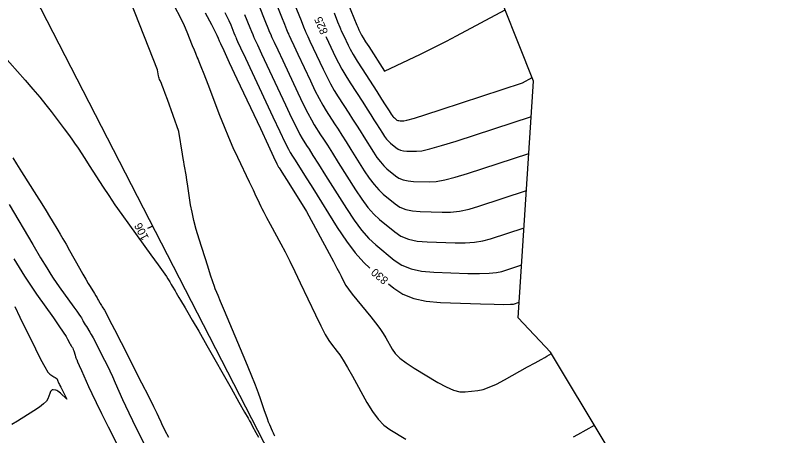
# Model space of a CAD drawing. Extents: x 1715724 to 1716561, y 394063 to 395906.
# Drawn here: x 1716070.7 to 1716206.5, y 394949.5 to 395022.9 of the extents above; entities that cross this region are included whole.
import ezdxf

# ---------------------------------------------------------------- set-up
doc = ezdxf.new("R2010")
doc.units = 0
for name, color, linetype in [('DT_X_Contour_Major', 7, 'Continuous'), ('DT_X_Contour_Minor', 7, 'Continuous'), ('DT_X_TIN_Hull', 7, 'Continuous'), ('GE_P_CL_10', 7, 'Continuous')]:
    doc.layers.add(name, color=color, linetype=linetype)

msp = doc.modelspace()

# ---------------------------------------------------------------- linework, layer by layer
at = {"layer": 'DT_X_Contour_Major'}
for points in [[(1716107.28, 395023.4), (1716107.97, 395022.03), (1716108.33, 395021.24), (1716108.89, 395019.87), (1716109.07, 395019.42), (1716109.2, 395019.09), (1716109.29, 395018.88), (1716109.32, 395018.8), (1716109.35, 395018.73), (1716109.53, 395018.35), (1716110.05, 395017.25), (1716110.9, 395015.44), (1716112.08, 395012.91), (1716115.7, 395005.2), (1716116.9, 395002.65), (1716117.81, 395000.75), (1716118.41, 394999.52), (1716118.72, 394998.95), (1716119.13, 394998.31), (1716119.47, 394997.77), (1716120.17, 394996.66), (1716121.24, 394994.97), (1716122.67, 394992.7), (1716126.96, 394985.85), (1716128.55, 394983.46), (1716130.1, 394981.42), (1716131.59, 394979.73), (1716132.67, 394978.73)], [(1716124.96, 395019.21), (1716125.01, 395019.12), (1716125.41, 395018.25), (1716126.65, 395015.61), (1716127.16, 395014.59), (1716127.75, 395013.5), (1716128.44, 395012.34), (1716129.21, 395011.1), (1716131.4, 395007.73), (1716132.16, 395006.54), (1716132.82, 395005.52), (1716133.37, 395004.66), (1716133.81, 395003.97), (1716134.83, 395002.34), (1716135.21, 395001.77), (1716135.58, 395001.28), (1716135.94, 395000.88), (1716136.28, 395000.56), (1716137.19, 394999.81), (1716137.57, 394999.56), (1716138.01, 394999.38), (1716138.54, 394999.27), (1716139.13, 394999.21), (1716140.81, 394999.16), (1716141.71, 394999.26), (1716143.16, 394999.59), (1716145.16, 395000.16), (1716147.71, 395000.96), (1716160.88, 395005.27)], [(1716070.39, 394980.38), (1716071.31, 394978.86), (1716072.28, 394977.34), (1716073.3, 394975.79), (1716074.38, 394974.24), (1716077.32, 394970.08), (1716078.3, 394968.67), (1716079.04, 394967.59), (1716079.54, 394966.83), (1716079.8, 394966.38), (1716080.18, 394965.61), (1716080.3, 394965.36), (1716080.41, 394965.17), (1716080.48, 394965.05), (1716080.53, 394965), (1716080.63, 394964.94), (1716080.67, 394964.88), (1716080.73, 394964.76), (1716080.8, 394964.57), (1716080.89, 394964.31), (1716081.13, 394963.54), (1716081.21, 394963.29), (1716081.27, 394963.11), (1716081.31, 394963), (1716081.32, 394962.95), (1716081.33, 394962.94), (1716081.39, 394962.8), (1716081.56, 394962.41), (1716081.85, 394961.76), (1716082.25, 394960.86), (1716083.48, 394958.09), (1716084.04, 394956.88), (1716084.8, 394955.29), (1716085.76, 394953.35), (1716086.92, 394951.04), (1716091.41, 394942.22)], [(1716135.89, 394976.05), (1716136.85, 394975.26), (1716138.43, 394974.23), (1716140.31, 394973.47), (1716142.5, 394972.97), (1716144.98, 394972.75), (1716152.02, 394972.53), (1716154.36, 394972.46), (1716156.09, 394972.44), (1716157.22, 394972.45), (1716157.74, 394972.5), (1716158.78, 394972.84)]]:
    msp.add_lwpolyline(points, dxfattribs=at)
at = {"layer": 'DT_X_Contour_Minor'}
for points in [[(1716118.04, 395028.39), (1716120.61, 395022.02), (1716121.07, 395020.89), (1716121.34, 395020.21), (1716121.44, 395019.97), (1716121.45, 395019.94), (1716121.78, 395019.24), (1716122.18, 395018.38), (1716122.75, 395017.18), (1716124.46, 395013.53), (1716125.11, 395012.2), (1716125.76, 395010.95), (1716126.43, 395009.77), (1716127.11, 395008.67), (1716128.95, 395005.84), (1716129.62, 395004.79), (1716130.29, 395003.75), (1716130.94, 395002.72), (1716131.58, 395001.71), (1716133.26, 394999.04), (1716133.88, 394998.11), (1716134.48, 394997.31), (1716135.07, 394996.65), (1716135.63, 394996.12), (1716137.12, 394994.9), (1716137.74, 394994.5), (1716138.47, 394994.2), (1716139.33, 394994.01), (1716140.3, 394993.92), (1716143.05, 394993.83), (1716144.24, 394993.9), (1716145.75, 394994.16), (1716147.57, 394994.62), (1716149.72, 394995.27), (1716160.46, 394998.79)], [(1716115.61, 395026.6), (1716117.2, 395022.66), (1716117.72, 395021.37), (1716118.1, 395020.44), (1716118.33, 395019.88), (1716118.41, 395019.68), (1716118.43, 395019.64), (1716118.54, 395019.41), (1716118.85, 395018.74), (1716119.36, 395017.65), (1716120.08, 395016.11), (1716122.27, 395011.45), (1716123.05, 395009.81), (1716123.77, 395008.4), (1716124.43, 395007.21), (1716125.02, 395006.24), (1716126.49, 395003.96), (1716127.09, 395003.03), (1716127.76, 395001.98), (1716128.51, 395000.79), (1716129.35, 394999.46), (1716131.68, 394995.74), (1716132.55, 394994.45), (1716133.39, 394993.34), (1716134.2, 394992.42), (1716134.99, 394991.69), (1716137.05, 394989.99), (1716137.91, 394989.43), (1716138.93, 394989.02), (1716140.12, 394988.75), (1716141.47, 394988.63), (1716145.29, 394988.51), (1716146.77, 394988.54), (1716148.33, 394988.73), (1716149.99, 394989.08), (1716151.72, 394989.58), (1716160.04, 394992.3)], [(1716128.29, 395026.38), (1716130.38, 395021.2), (1716130.53, 395020.85), (1716130.54, 395020.82), (1716130.74, 395020.39), (1716131.03, 395019.78), (1716131.2, 395019.46), (1716131.49, 395018.97), (1716131.9, 395018.31), (1716132.44, 395017.48), (1716135.22, 395013.17), (1716141.48, 395016.14), (1716142.88, 395016.82), (1716144.4, 395017.58), (1716146.04, 395018.42), (1716147.81, 395019.35), (1716156.31, 395023.89)], [(1716116.03, 394949.43), (1716115.94, 394949.64), (1716115.81, 394949.94), (1716115.64, 394950.31), (1716115.14, 394951.41), (1716114.94, 394951.87), (1716114.73, 394952.43), (1716114.5, 394953.08), (1716114.24, 394953.82), (1716113.55, 394955.93), (1716113.19, 394956.93), (1716112.64, 394958.35), (1716111.89, 394960.2), (1716110.95, 394962.47), (1716108.17, 394969.08), (1716107.25, 394971.28), (1716106.56, 394972.92), (1716106.11, 394974), (1716105.89, 394974.51), (1716105.63, 394975.14), (1716105.47, 394975.57), (1716105.2, 394976.37), (1716104.81, 394977.56), (1716104.31, 394979.13), (1716102.83, 394983.82), (1716102.31, 394985.52), (1716101.89, 394987.08), (1716101.56, 394988.51), (1716101.32, 394989.81), (1716100.81, 394993.1), (1716100.64, 394994.21), (1716100.51, 394995.06), (1716100.41, 394995.66), (1716100.35, 394996), (1716100.26, 394996.58), (1716100.21, 394996.87), (1716100.13, 394997.32), (1716100.03, 394997.93), (1716099.9, 394998.69), (1716099.23, 395002.61), (1716097.25, 395008.2), (1716096.87, 395009.27), (1716096.57, 395010.09), (1716096.36, 395010.66), (1716096.22, 395010.99), (1716095.99, 395011.52), (1716095.9, 395011.72), (1716095.83, 395011.93), (1716095.77, 395012.14), (1716095.72, 395012.35), (1716095.52, 395013.37), (1716090.84, 395025.22)], [(1716098.49, 395024.46), (1716099.47, 395022.59), (1716100.19, 395021.11), (1716100.67, 395020.03), (1716101.61, 395017.64), (1716101.92, 395016.86), (1716102.14, 395016.29), (1716102.28, 395015.94), (1716102.33, 395015.81), (1716102.36, 395015.75), (1716102.37, 395015.72), (1716102.4, 395015.66), (1716102.43, 395015.58), (1716102.48, 395015.48), (1716102.63, 395015.17), (1716102.77, 395014.82), (1716103.1, 395013.98), (1716103.61, 395012.67), (1716104.3, 395010.88), (1716106.38, 395005.46), (1716107.16, 395003.48), (1716107.94, 395001.61), (1716108.71, 394999.84), (1716109.48, 394998.17), (1716111.53, 394993.85), (1716112.22, 394992.41), (1716112.74, 394991.31), (1716113.1, 394990.55), (1716113.29, 394990.15), (1716113.59, 394989.53), (1716113.77, 394989.16), (1716114.11, 394988.53), (1716114.59, 394987.63), (1716115.22, 394986.46), (1716117.09, 394983), (1716117.83, 394981.6), (1716118.64, 394980), (1716119.53, 394978.2), (1716120.49, 394976.2), (1716123.16, 394970.59), (1716124.08, 394968.69), (1716124.85, 394967.2), (1716125.47, 394966.13), (1716125.93, 394965.46), (1716126.94, 394964.23), (1716127.4, 394963.61), (1716127.99, 394962.68), (1716128.73, 394961.43), (1716129.61, 394959.87), (1716132.13, 394955.29), (1716133.1, 394953.71), (1716134.08, 394952.4), (1716135.1, 394951.36), (1716136.14, 394950.59), (1716138.94, 394948.9)], [(1716113.18, 395024.81), (1716114.43, 395021.73), (1716114.84, 395020.72), (1716115.13, 395019.99), (1716115.31, 395019.54), (1716115.38, 395019.38), (1716115.4, 395019.34), (1716115.53, 395019.06), (1716115.91, 395018.25), (1716116.54, 395016.91), (1716117.42, 395015.04), (1716120.08, 395009.37), (1716121, 395007.42), (1716121.79, 395005.85), (1716122.42, 395004.64), (1716122.92, 395003.81), (1716124.04, 395002.07), (1716124.55, 395001.28), (1716125.23, 395000.21), (1716126.09, 394998.85), (1716127.12, 394997.2), (1716130.11, 394992.45), (1716131.22, 394990.79), (1716132.29, 394989.37), (1716133.33, 394988.19), (1716134.34, 394987.25), (1716136.99, 394985.08), (1716138.08, 394984.36), (1716139.39, 394983.83), (1716140.91, 394983.49), (1716142.64, 394983.34), (1716147.54, 394983.18), (1716149.3, 394983.18), (1716150.92, 394983.3), (1716152.4, 394983.53), (1716153.73, 394983.89), (1716159.62, 394985.81)], [(1716103.88, 395023.32), (1716104.96, 395021.3), (1716105.63, 395020.01), (1716105.91, 395019.45), (1716106.11, 395018.94), (1716106.18, 395018.77), (1716106.24, 395018.64), (1716106.27, 395018.55), (1716106.29, 395018.5), (1716106.33, 395018.43), (1716106.53, 395018), (1716107.11, 395016.75), (1716108.08, 395014.7), (1716109.42, 395011.84), (1716113.51, 395003.12), (1716114.85, 395000.26), (1716115.82, 394998.2), (1716116.41, 394996.95), (1716116.62, 394996.51), (1716116.68, 394996.42), (1716116.79, 394996.25), (1716117.07, 394995.79), (1716117.54, 394995.05), (1716118.18, 394994.04), (1716121.57, 394988.64), (1716125.52, 394981.33), (1716126.28, 394979.91), (1716126.89, 394978.78), (1716127.33, 394977.93), (1716127.61, 394977.37), (1716128.14, 394976.25), (1716128.43, 394975.75), (1716128.89, 394975.07), (1716129.54, 394974.22), (1716130.36, 394973.2), (1716132.8, 394970.26), (1716133.65, 394969.2), (1716134.37, 394968.23), (1716134.97, 394967.36), (1716135.44, 394966.58), (1716136.52, 394964.62), (1716137.07, 394963.86), (1716137.9, 394963.05), (1716139.02, 394962.2), (1716140.42, 394961.29), (1716144.54, 394958.82), (1716146, 394958.02), (1716147.27, 394957.47), (1716148.37, 394957.18), (1716149.3, 394957.15), (1716151.52, 394957.4), (1716152.44, 394957.58), (1716153.53, 394957.96), (1716154.78, 394958.51), (1716156.2, 394959.26), (1716160.22, 394961.5), (1716161.56, 394962.25), (1716162.57, 394962.81), (1716163.24, 394963.18), (1716163.59, 394963.37), (1716164.41, 394963.83)], [(1716110.76, 395023.03), (1716111.66, 395020.8), (1716111.95, 395020.07), (1716112.17, 395019.54), (1716112.3, 395019.21), (1716112.35, 395019.09), (1716112.38, 395019.04), (1716112.53, 395018.7), (1716112.98, 395017.75), (1716113.72, 395016.17), (1716117.89, 395007.29), (1716118.95, 395005.03), (1716119.8, 395003.3), (1716120.42, 395002.08), (1716120.82, 395001.38), (1716121.58, 395000.19), (1716122.01, 394999.53), (1716122.7, 394998.43), (1716123.66, 394996.91), (1716124.89, 394994.95), (1716128.54, 394989.15), (1716129.88, 394987.12), (1716131.19, 394985.39), (1716132.46, 394983.96), (1716133.69, 394982.82), (1716136.92, 394980.17), (1716138.26, 394979.3), (1716139.85, 394978.65), (1716141.7, 394978.23), (1716143.81, 394978.05), (1716149.78, 394977.85), (1716151.83, 394977.82), (1716153.51, 394977.87), (1716154.81, 394977.99), (1716155.74, 394978.2), (1716159.2, 394979.33)], [(1716126.38, 395023.32), (1716127, 395021.79), (1716127.37, 395020.87), (1716127.5, 395020.56), (1716127.5, 395020.55), (1716127.54, 395020.47), (1716127.65, 395020.24), (1716127.83, 395019.85), (1716128.08, 395019.32), (1716128.84, 395017.7), (1716129.21, 395016.98), (1716129.74, 395016.05), (1716130.45, 395014.9), (1716131.31, 395013.54), (1716133.85, 395009.61), (1716134.7, 395008.29), (1716135.35, 395007.29), (1716135.79, 395006.6), (1716136.03, 395006.22), (1716136.4, 395005.63), (1716136.54, 395005.43), (1716136.67, 395005.25), (1716136.8, 395005.11), (1716136.93, 395004.99), (1716137.26, 395004.72), (1716137.39, 395004.63), (1716137.56, 395004.57), (1716137.74, 395004.52), (1716137.96, 395004.5), (1716138.57, 395004.49), (1716139.14, 395004.6), (1716140.43, 395004.97), (1716142.42, 395005.59), (1716145.11, 395006.46), (1716159.32, 395011.11), (1716161.04, 395012.03)], [(1716065.63, 395019.14), (1716072.36, 395011.6), (1716073.73, 395010.04), (1716074.95, 395008.61), (1716076.01, 395007.3), (1716076.93, 395006.11), (1716079.19, 395003.11), (1716079.94, 395002.09), (1716080.52, 395001.31), (1716080.92, 395000.76), (1716081.15, 395000.44), (1716081.51, 394999.88), (1716081.74, 394999.52), (1716082.17, 394998.87), (1716082.79, 394997.91), (1716083.6, 394996.66), (1716086.03, 394992.92), (1716087, 394991.45), (1716088.09, 394989.84), (1716089.31, 394988.11), (1716090.64, 394986.24), (1716094.37, 394981.07), (1716095.61, 394979.36), (1716096.51, 394978.1), (1716097.09, 394977.28), (1716097.34, 394976.91), (1716097.57, 394976.53), (1716097.67, 394976.37), (1716097.79, 394976.16), (1716097.94, 394975.91), (1716098.11, 394975.62), (1716098.59, 394974.78), (1716098.78, 394974.44), (1716099.01, 394974.06), (1716099.27, 394973.63), (1716099.56, 394973.15), (1716100.36, 394971.83), (1716100.83, 394971.04), (1716101.61, 394969.68), (1716102.72, 394967.76), (1716104.15, 394965.25), (1716108.38, 394957.82), (1716109.77, 394955.38), (1716110.76, 394953.63), (1716111.36, 394952.57), (1716111.57, 394952.21), (1716111.59, 394952.18), (1716111.62, 394952.11), (1716111.72, 394951.93), (1716111.87, 394951.65), (1716112.09, 394951.25), (1716112.74, 394950.06), (1716112.97, 394949.64), (1716113.17, 394949.27)], [(1716070.25, 394998.03), (1716070.9, 394996.99), (1716071.77, 394995.6), (1716074.39, 394991.42), (1716075.29, 394989.97), (1716076.04, 394988.76), (1716076.65, 394987.79), (1716077.1, 394987.05), (1716078.1, 394985.39), (1716078.51, 394984.7), (1716078.99, 394983.88), (1716079.53, 394982.92), (1716080.15, 394981.84), (1716081.88, 394978.76), (1716082.48, 394977.7), (1716082.99, 394976.81), (1716083.41, 394976.09), (1716083.74, 394975.54), (1716084.49, 394974.32), (1716084.74, 394973.91), (1716084.95, 394973.57), (1716085.11, 394973.3), (1716085.21, 394973.12), (1716085.43, 394972.73), (1716085.52, 394972.57), (1716085.62, 394972.4), (1716085.74, 394972.21), (1716085.87, 394972), (1716086.23, 394971.43), (1716086.52, 394970.92), (1716087.1, 394969.8), (1716087.99, 394968.07), (1716089.18, 394965.75), (1716092.74, 394958.74), (1716093.92, 394956.4), (1716094.81, 394954.63), (1716095.4, 394953.44), (1716095.7, 394952.82), (1716096.09, 394951.95), (1716096.24, 394951.61), (1716096.41, 394951.24), (1716096.61, 394950.84), (1716096.82, 394950.42), (1716097.42, 394949.24)], [(1716069.58, 394989.89), (1716073.71, 394982.91), (1716075.09, 394980.57), (1716076.15, 394978.81), (1716076.87, 394977.63), (1716077.27, 394977.02), (1716078.34, 394975.5), (1716080.92, 394971.95), (1716081.41, 394971.27), (1716081.79, 394970.73), (1716082.06, 394970.33), (1716082.21, 394970.08), (1716082.44, 394969.61), (1716082.55, 394969.42), (1716082.69, 394969.17), (1716082.87, 394968.88), (1716083.08, 394968.55), (1716083.68, 394967.6), (1716083.94, 394967.17), (1716084.25, 394966.62), (1716084.62, 394965.93), (1716085.05, 394965.1), (1716086.26, 394962.72), (1716086.71, 394961.8), (1716087.18, 394960.83), (1716087.65, 394959.82), (1716088.13, 394958.75), (1716089.42, 394955.84), (1716089.93, 394954.7), (1716090.52, 394953.47), (1716091.16, 394952.15), (1716091.87, 394950.73), (1716093.86, 394946.82)], [(1716070.56, 394972.07), (1716071.48, 394970.2), (1716074.17, 394964.68), (1716075.08, 394962.85), (1716075.81, 394961.5), (1716076.36, 394960.62), (1716076.71, 394960.22), (1716077.41, 394959.8), (1716077.65, 394959.65), (1716077.81, 394959.54), (1716077.92, 394959.46), (1716077.96, 394959.41), (1716077.99, 394959.32), (1716078, 394959.29), (1716078.01, 394959.26), (1716078.02, 394959.24), (1716078.03, 394959.22), (1716078.05, 394959.18), (1716078.06, 394959.15), (1716078.09, 394959.09), (1716078.12, 394959.02), (1716078.17, 394958.92), (1716078.3, 394958.61), (1716078.37, 394958.47), (1716078.47, 394958.25), (1716078.61, 394957.98), (1716078.78, 394957.63), (1716079.67, 394955.88), (1716078.54, 394956.93), (1716078.31, 394957.13), (1716078.1, 394957.28), (1716077.9, 394957.39), (1716077.73, 394957.44), (1716077.28, 394957.54), (1716077.12, 394957.53), (1716076.97, 394957.41), (1716076.83, 394957.2), (1716076.69, 394956.89), (1716076.35, 394955.94), (1716076.1, 394955.54), (1716075.61, 394955.06), (1716074.89, 394954.5), (1716073.92, 394953.87), (1716071.04, 394952.06), (1716070.05, 394951.46)], [(1716168.26, 394949.32), (1716169.03, 394949.72), (1716171.92, 394951.32)]]:
    msp.add_lwpolyline(points, dxfattribs=at)
at = {"layer": 'DT_X_TIN_Hull'}
msp.add_lwpolyline([(1716173.81, 394948.17), (1716164.24, 394964.1), (1716158.6, 394970.07), (1716161.28, 395011.43), (1716153.51, 395030.9), (1716140.07, 395054.98), (1716157.64, 395075.49), (1716176.81, 395091.39), (1716197.29, 395109.75), (1716218.02, 395125.43), (1716237.91, 395140.5), (1716261.28, 395153.34), (1716300.31, 395170.24), (1716324.76, 395179.27), (1716349.42, 395190.19), (1716344.96, 395206.21), (1716337.66, 395219.83)], dxfattribs=at)
at = {"layer": 'GE_P_CL_10'}
for p, q in [((1716249.46, 394685.42), (1715852.54, 395456.56)), ((1716094.69, 394986.12), (1716093.8, 394985.66))]:
    msp.add_line(p, q, dxfattribs=at)

# ---------------------------------------------------------------- texts
at = {"layer": 'DT_X_Contour_Major'}
for s, rotation, p in [('825', 112.8853, (1716125.38, 395019.95)), ('830', 140.2268, (1716136, 394976.85))]:
    msp.add_text(s, height=1.4, rotation=rotation, dxfattribs=at).set_placement(p)
at = {"layer": 'GE_P_CL_10'}
msp.add_text('106', height=1.4, rotation=117.2357, dxfattribs=at).set_placement((1716094.06, 394984.06))

doc.saveas('drawing.dxf')
